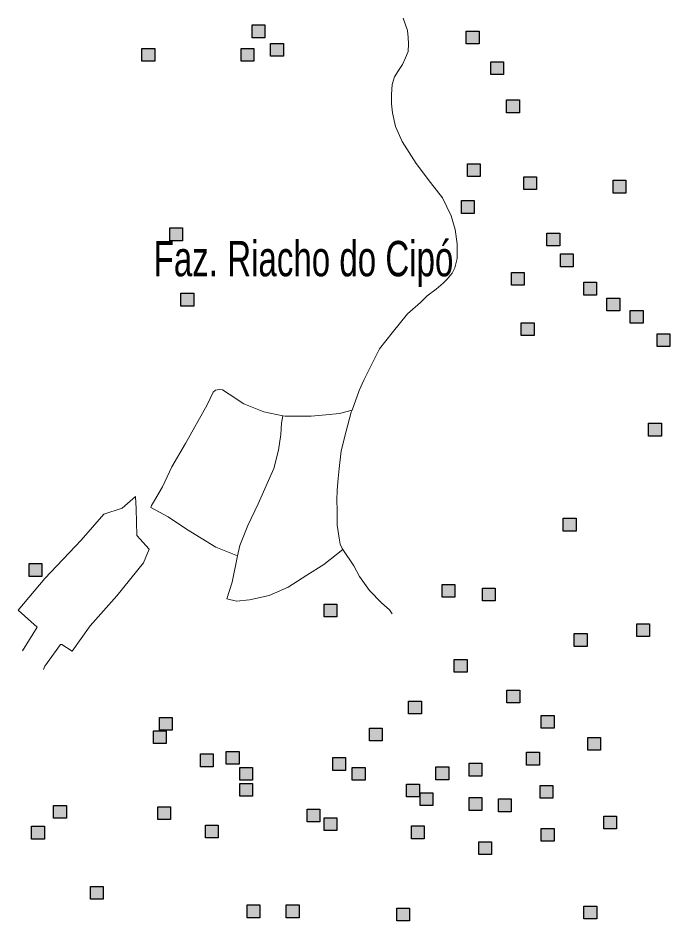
# Model space of a CAD drawing. Extents: x 445.6 to 500, y 8618.1 to 8673.4.
# Drawn here: x 466.846 to 469.797, y 8626.513 to 8630.601 of the extents above; entities that cross this region are included whole.
import ezdxf

# ---------------------------------------------------------------- set-up
doc = ezdxf.new("R2010")
doc.units = 0
doc.header["$LTSCALE"] = 0.064
doc.linetypes.add('DOT_DASHED', pattern=[7.7, 5, -1.2, 0.3, -1.2])
doc.layers.add('2', color=7, linetype='Continuous', lineweight=25)
doc.layers.add('22', color=7, linetype='DOT_DASHED', lineweight=13)
doc.layers.add('61', color=7, linetype='Continuous')

msp = doc.modelspace()

# ---------------------------------------------------------------- hatches: boundary and pattern name
at = {"layer": '2'}
for points in [[(467.9059, 8630.5696), (467.9639, 8630.5696), (467.9639, 8630.5116), (467.9059, 8630.5116)], [(468.875, 8630.5417), (468.933, 8630.5417), (468.933, 8630.4837), (468.875, 8630.4837)], [(467.9891, 8630.4862), (468.0471, 8630.4862), (468.0471, 8630.4282), (467.9891, 8630.4282)], [(467.4065, 8630.4639), (467.4645, 8630.4639), (467.4645, 8630.4059), (467.4065, 8630.4059)], [(467.8561, 8630.4639), (467.9141, 8630.4639), (467.9141, 8630.4059), (467.8561, 8630.4059)], [(468.9859, 8630.4028), (469.0439, 8630.4028), (469.0439, 8630.3448), (468.9859, 8630.3448)], [(469.0579, 8630.2305), (469.1159, 8630.2305), (469.1159, 8630.1725), (469.0579, 8630.1725)], [(468.8806, 8629.9415), (468.9386, 8629.9415), (468.9386, 8629.8835), (468.8806, 8629.8835)], [(469.1355, 8629.8828), (469.1935, 8629.8828), (469.1935, 8629.8248), (469.1355, 8629.8248)], [(469.5396, 8629.8663), (469.5976, 8629.8663), (469.5976, 8629.8083), (469.5396, 8629.8083)], [(468.8529, 8629.7747), (468.9109, 8629.7747), (468.9109, 8629.7167), (468.8529, 8629.7167)], [(467.5327, 8629.6508), (467.5907, 8629.6508), (467.5907, 8629.5928), (467.5327, 8629.5928)], [(469.2404, 8629.6273), (469.2984, 8629.6273), (469.2984, 8629.5693), (469.2404, 8629.5693)], [(469.3013, 8629.5328), (469.3593, 8629.5328), (469.3593, 8629.4748), (469.3013, 8629.4748)], [(469.0797, 8629.4495), (469.1377, 8629.4495), (469.1377, 8629.3915), (469.0797, 8629.3915)], [(469.4066, 8629.405), (469.4646, 8629.405), (469.4646, 8629.347), (469.4066, 8629.347)], [(467.5834, 8629.355), (467.6414, 8629.355), (467.6414, 8629.297), (467.5834, 8629.297)], [(469.5119, 8629.3333), (469.5699, 8629.3333), (469.5699, 8629.2753), (469.5119, 8629.2753)], [(469.6172, 8629.2772), (469.6752, 8629.2772), (469.6752, 8629.2192), (469.6172, 8629.2192)], [(469.124, 8629.2216), (469.182, 8629.2216), (469.182, 8629.1636), (469.124, 8629.1636)], [(469.7391, 8629.1716), (469.7971, 8629.1716), (469.7971, 8629.1136), (469.7391, 8629.1136)], [(469.7003, 8628.7663), (469.7583, 8628.7663), (469.7583, 8628.7083), (469.7003, 8628.7083)], [(469.3142, 8628.3364), (469.3722, 8628.3364), (469.3722, 8628.2784), (469.3142, 8628.2784)], [(466.8962, 8628.1307), (466.9542, 8628.1307), (466.9542, 8628.0727), (466.8962, 8628.0727)], [(468.7655, 8628.0363), (468.8235, 8628.0363), (468.8235, 8627.9783), (468.7655, 8627.9783)], [(468.9484, 8628.0196), (469.0064, 8628.0196), (469.0064, 8627.9616), (468.9484, 8627.9616)], [(468.2317, 8627.9473), (468.2897, 8627.9473), (468.2897, 8627.8893), (468.2317, 8627.8893)], [(469.6467, 8627.8584), (469.7047, 8627.8584), (469.7047, 8627.8004), (469.6467, 8627.8004)], [(469.364, 8627.814), (469.422, 8627.814), (469.422, 8627.756), (469.364, 8627.756)], [(468.821, 8627.6973), (468.879, 8627.6973), (468.879, 8627.6393), (468.821, 8627.6393)], [(469.0592, 8627.5583), (469.1172, 8627.5583), (469.1172, 8627.5003), (469.0592, 8627.5003)], [(468.6141, 8627.5082), (468.6721, 8627.5082), (468.6721, 8627.4502), (468.6141, 8627.4502)], [(467.4856, 8627.4343), (467.5436, 8627.4343), (467.5436, 8627.3763), (467.4856, 8627.3763)], [(469.2146, 8627.4434), (469.2726, 8627.4434), (469.2726, 8627.3854), (469.2146, 8627.3854)], [(467.4588, 8627.3738), (467.5168, 8627.3738), (467.5168, 8627.3158), (467.4588, 8627.3158)], [(468.4368, 8627.3859), (468.4948, 8627.3859), (468.4948, 8627.3279), (468.4368, 8627.3279)], [(469.4251, 8627.3434), (469.4831, 8627.3434), (469.4831, 8627.2854), (469.4251, 8627.2854)], [(467.672, 8627.2692), (467.73, 8627.2692), (467.73, 8627.2112), (467.672, 8627.2112)], [(467.7884, 8627.2803), (467.8464, 8627.2803), (467.8464, 8627.2223), (467.7884, 8627.2223)], [(468.2705, 8627.2525), (468.3285, 8627.2525), (468.3285, 8627.1945), (468.2705, 8627.1945)], [(469.1481, 8627.2767), (469.2061, 8627.2767), (469.2061, 8627.2187), (469.1481, 8627.2187)], [(467.8494, 8627.208), (467.9074, 8627.208), (467.9074, 8627.15), (467.8494, 8627.15)], [(468.3592, 8627.208), (468.4172, 8627.208), (468.4172, 8627.15), (468.3592, 8627.15)], [(468.738, 8627.21), (468.796, 8627.21), (468.796, 8627.152), (468.738, 8627.152)], [(468.8876, 8627.2267), (468.9456, 8627.2267), (468.9456, 8627.1687), (468.8876, 8627.1687)], [(467.8494, 8627.1358), (467.9074, 8627.1358), (467.9074, 8627.0778), (467.8494, 8627.0778)], [(468.605, 8627.1322), (468.663, 8627.1322), (468.663, 8627.0742), (468.605, 8627.0742)], [(469.209, 8627.1266), (469.267, 8627.1266), (469.267, 8627.0686), (469.209, 8627.0686)], [(468.6659, 8627.0933), (468.7239, 8627.0933), (468.7239, 8627.0353), (468.6659, 8627.0353)], [(468.8876, 8627.071), (468.9456, 8627.071), (468.9456, 8627.013), (468.8876, 8627.013)], [(469.0206, 8627.0655), (469.0786, 8627.0655), (469.0786, 8627.0075), (469.0206, 8627.0075)], [(467.007, 8627.0357), (467.065, 8627.0357), (467.065, 8626.9777), (467.007, 8626.9777)], [(467.4781, 8627.0302), (467.5361, 8627.0302), (467.5361, 8626.9722), (467.4781, 8626.9722)], [(468.1541, 8627.0191), (468.2121, 8627.0191), (468.2121, 8626.9611), (468.1541, 8626.9611)], [(468.2317, 8626.9802), (468.2897, 8626.9802), (468.2897, 8626.9222), (468.2317, 8626.9222)], [(469.4972, 8626.9877), (469.5552, 8626.9877), (469.5552, 8626.9297), (469.4972, 8626.9297)], [(466.9073, 8626.9412), (466.9653, 8626.9412), (466.9653, 8626.8832), (466.9073, 8626.8832)], [(467.6942, 8626.9468), (467.7522, 8626.9468), (467.7522, 8626.8888), (467.6942, 8626.8888)], [(468.6271, 8626.9432), (468.6851, 8626.9432), (468.6851, 8626.8852), (468.6271, 8626.8852)], [(469.2146, 8626.9321), (469.2726, 8626.9321), (469.2726, 8626.8741), (469.2146, 8626.8741)], [(468.9319, 8626.8709), (468.9899, 8626.8709), (468.9899, 8626.8129), (468.9319, 8626.8129)], [(467.1733, 8626.6689), (467.2313, 8626.6689), (467.2313, 8626.6109), (467.1733, 8626.6109)], [(467.8826, 8626.5855), (467.9406, 8626.5855), (467.9406, 8626.5275), (467.8826, 8626.5275)], [(468.0599, 8626.5855), (468.1179, 8626.5855), (468.1179, 8626.5275), (468.0599, 8626.5275)], [(468.5606, 8626.5708), (468.6186, 8626.5708), (468.6186, 8626.5128), (468.5606, 8626.5128)], [(469.4075, 8626.58), (469.4655, 8626.58), (469.4655, 8626.522), (469.4075, 8626.522)]]:
    msp.add_hatch(color=256, dxfattribs=at).paths.add_polyline_path(points)

# ---------------------------------------------------------------- linework, layer by layer
for points in [[(467.9059, 8630.5696), (467.9639, 8630.5696), (467.9639, 8630.5116), (467.9059, 8630.5116)], [(468.875, 8630.5417), (468.933, 8630.5417), (468.933, 8630.4837), (468.875, 8630.4837)], [(467.9891, 8630.4862), (468.0471, 8630.4862), (468.0471, 8630.4282), (467.9891, 8630.4282)], [(467.4065, 8630.4639), (467.4645, 8630.4639), (467.4645, 8630.4059), (467.4065, 8630.4059)], [(467.8561, 8630.4639), (467.9141, 8630.4639), (467.9141, 8630.4059), (467.8561, 8630.4059)], [(468.9859, 8630.4028), (469.0439, 8630.4028), (469.0439, 8630.3448), (468.9859, 8630.3448)], [(469.0579, 8630.2305), (469.1159, 8630.2305), (469.1159, 8630.1725), (469.0579, 8630.1725)], [(468.8806, 8629.9415), (468.9386, 8629.9415), (468.9386, 8629.8835), (468.8806, 8629.8835)], [(469.1355, 8629.8828), (469.1935, 8629.8828), (469.1935, 8629.8248), (469.1355, 8629.8248)], [(469.5396, 8629.8663), (469.5976, 8629.8663), (469.5976, 8629.8083), (469.5396, 8629.8083)], [(468.8529, 8629.7747), (468.9109, 8629.7747), (468.9109, 8629.7167), (468.8529, 8629.7167)], [(467.5327, 8629.6508), (467.5907, 8629.6508), (467.5907, 8629.5928), (467.5327, 8629.5928)], [(469.2404, 8629.6273), (469.2984, 8629.6273), (469.2984, 8629.5693), (469.2404, 8629.5693)], [(469.3013, 8629.5328), (469.3593, 8629.5328), (469.3593, 8629.4748), (469.3013, 8629.4748)], [(469.0797, 8629.4495), (469.1377, 8629.4495), (469.1377, 8629.3915), (469.0797, 8629.3915)], [(469.4066, 8629.405), (469.4646, 8629.405), (469.4646, 8629.347), (469.4066, 8629.347)], [(467.5834, 8629.355), (467.6414, 8629.355), (467.6414, 8629.297), (467.5834, 8629.297)], [(469.5119, 8629.3333), (469.5699, 8629.3333), (469.5699, 8629.2753), (469.5119, 8629.2753)], [(469.6172, 8629.2772), (469.6752, 8629.2772), (469.6752, 8629.2192), (469.6172, 8629.2192)], [(469.124, 8629.2216), (469.182, 8629.2216), (469.182, 8629.1636), (469.124, 8629.1636)], [(469.7391, 8629.1716), (469.7971, 8629.1716), (469.7971, 8629.1136), (469.7391, 8629.1136)], [(469.7003, 8628.7663), (469.7583, 8628.7663), (469.7583, 8628.7083), (469.7003, 8628.7083)], [(469.3142, 8628.3364), (469.3722, 8628.3364), (469.3722, 8628.2784), (469.3142, 8628.2784)], [(466.8962, 8628.1307), (466.9542, 8628.1307), (466.9542, 8628.0727), (466.8962, 8628.0727)], [(468.7655, 8628.0363), (468.8235, 8628.0363), (468.8235, 8627.9783), (468.7655, 8627.9783)], [(468.9484, 8628.0196), (469.0064, 8628.0196), (469.0064, 8627.9616), (468.9484, 8627.9616)], [(468.2317, 8627.9473), (468.2897, 8627.9473), (468.2897, 8627.8893), (468.2317, 8627.8893)], [(469.6467, 8627.8584), (469.7047, 8627.8584), (469.7047, 8627.8004), (469.6467, 8627.8004)], [(469.364, 8627.814), (469.422, 8627.814), (469.422, 8627.756), (469.364, 8627.756)], [(468.821, 8627.6973), (468.879, 8627.6973), (468.879, 8627.6393), (468.821, 8627.6393)], [(469.0592, 8627.5583), (469.1172, 8627.5583), (469.1172, 8627.5003), (469.0592, 8627.5003)], [(468.6141, 8627.5082), (468.6721, 8627.5082), (468.6721, 8627.4502), (468.6141, 8627.4502)], [(467.4856, 8627.4343), (467.5436, 8627.4343), (467.5436, 8627.3763), (467.4856, 8627.3763)], [(469.2146, 8627.4434), (469.2726, 8627.4434), (469.2726, 8627.3854), (469.2146, 8627.3854)], [(467.4588, 8627.3738), (467.5168, 8627.3738), (467.5168, 8627.3158), (467.4588, 8627.3158)], [(468.4368, 8627.3859), (468.4948, 8627.3859), (468.4948, 8627.3279), (468.4368, 8627.3279)], [(469.4251, 8627.3434), (469.4831, 8627.3434), (469.4831, 8627.2854), (469.4251, 8627.2854)], [(467.672, 8627.2692), (467.73, 8627.2692), (467.73, 8627.2112), (467.672, 8627.2112)], [(467.7884, 8627.2803), (467.8464, 8627.2803), (467.8464, 8627.2223), (467.7884, 8627.2223)], [(468.2705, 8627.2525), (468.3285, 8627.2525), (468.3285, 8627.1945), (468.2705, 8627.1945)], [(469.1481, 8627.2767), (469.2061, 8627.2767), (469.2061, 8627.2187), (469.1481, 8627.2187)], [(467.8494, 8627.208), (467.9074, 8627.208), (467.9074, 8627.15), (467.8494, 8627.15)], [(468.3592, 8627.208), (468.4172, 8627.208), (468.4172, 8627.15), (468.3592, 8627.15)], [(468.738, 8627.21), (468.796, 8627.21), (468.796, 8627.152), (468.738, 8627.152)], [(468.8876, 8627.2267), (468.9456, 8627.2267), (468.9456, 8627.1687), (468.8876, 8627.1687)], [(467.8494, 8627.1358), (467.9074, 8627.1358), (467.9074, 8627.0778), (467.8494, 8627.0778)], [(468.605, 8627.1322), (468.663, 8627.1322), (468.663, 8627.0742), (468.605, 8627.0742)], [(469.209, 8627.1266), (469.267, 8627.1266), (469.267, 8627.0686), (469.209, 8627.0686)], [(468.6659, 8627.0933), (468.7239, 8627.0933), (468.7239, 8627.0353), (468.6659, 8627.0353)], [(468.8876, 8627.071), (468.9456, 8627.071), (468.9456, 8627.013), (468.8876, 8627.013)], [(469.0206, 8627.0655), (469.0786, 8627.0655), (469.0786, 8627.0075), (469.0206, 8627.0075)], [(467.007, 8627.0357), (467.065, 8627.0357), (467.065, 8626.9777), (467.007, 8626.9777)], [(467.4781, 8627.0302), (467.5361, 8627.0302), (467.5361, 8626.9722), (467.4781, 8626.9722)], [(468.1541, 8627.0191), (468.2121, 8627.0191), (468.2121, 8626.9611), (468.1541, 8626.9611)], [(468.2317, 8626.9802), (468.2897, 8626.9802), (468.2897, 8626.9222), (468.2317, 8626.9222)], [(469.4972, 8626.9877), (469.5552, 8626.9877), (469.5552, 8626.9297), (469.4972, 8626.9297)], [(466.9073, 8626.9412), (466.9653, 8626.9412), (466.9653, 8626.8832), (466.9073, 8626.8832)], [(467.6942, 8626.9468), (467.7522, 8626.9468), (467.7522, 8626.8888), (467.6942, 8626.8888)], [(468.6271, 8626.9432), (468.6851, 8626.9432), (468.6851, 8626.8852), (468.6271, 8626.8852)], [(469.2146, 8626.9321), (469.2726, 8626.9321), (469.2726, 8626.8741), (469.2146, 8626.8741)], [(468.9319, 8626.8709), (468.9899, 8626.8709), (468.9899, 8626.8129), (468.9319, 8626.8129)], [(467.1733, 8626.6689), (467.2313, 8626.6689), (467.2313, 8626.6109), (467.1733, 8626.6109)], [(467.8826, 8626.5855), (467.9406, 8626.5855), (467.9406, 8626.5275), (467.8826, 8626.5275)], [(468.0599, 8626.5855), (468.1179, 8626.5855), (468.1179, 8626.5275), (468.0599, 8626.5275)], [(468.5606, 8626.5708), (468.6186, 8626.5708), (468.6186, 8626.5128), (468.5606, 8626.5128)], [(469.4075, 8626.58), (469.4655, 8626.58), (469.4655, 8626.522), (469.4075, 8626.522)]]:
    msp.add_lwpolyline(points, close=True, dxfattribs=at)
at = {"layer": '22'}
for points in [[(468.5887, 8630.601), (468.6093, 8630.5451), (468.6115, 8630.5134), (468.6138, 8630.4839), (468.6115, 8630.4499), (468.6002, 8630.4205), (468.5866, 8630.391), (468.5684, 8630.3638), (468.5503, 8630.3344), (468.5389, 8630.3004), (468.5367, 8630.2551), (468.5367, 8630.212), (468.5412, 8630.1712), (468.5548, 8630.1101), (468.5843, 8630.0421), (468.6478, 8629.9432), (468.7136, 8629.8571), (468.768, 8629.7868), (468.8066, 8629.7053), (468.8247, 8629.6441), (468.8338, 8629.5784), (468.8338, 8629.5127), (468.8228, 8629.4701), (468.8115, 8629.4452), (468.7888, 8629.418), (468.7707, 8629.3999), (468.7389, 8629.3727), (468.6981, 8629.3432), (468.6686, 8629.3138), (468.6096, 8629.2617), (468.5392, 8629.1756), (468.4825, 8629.1031), (468.4553, 8629.0487), (468.4114, 8628.9615), (468.3909, 8628.9139), (468.3582, 8628.8263)], [(468.0453, 8628.7998), (467.9592, 8628.8177), (467.8674, 8628.8536), (467.8016, 8628.8975), (467.7716, 8628.9174), (467.7576, 8628.9194), (467.7397, 8628.9154), (467.7297, 8628.9074), (467.7018, 8628.8496), (467.604, 8628.6743), (467.5421, 8628.5686), (467.5002, 8628.4789), (467.4635, 8628.416), (467.4496, 8628.394), (467.4476, 8628.3841), (467.5254, 8628.3422), (467.6092, 8628.2864), (467.741, 8628.2047), (467.84, 8628.1656)], [(468.3582, 8628.8263), (468.3005, 8628.8098), (468.2387, 8628.8038), (468.1728, 8628.7978), (468.055, 8628.7978), (468.0453, 8628.7998)], [(468.3582, 8628.8263), (468.3546, 8628.8165), (468.3319, 8628.7304), (468.3093, 8628.642), (468.3, 8628.5614), (468.2954, 8628.5161), (468.2909, 8628.464), (468.2886, 8628.4187), (468.2909, 8628.3734), (468.2909, 8628.3054), (468.3, 8628.2465), (468.3045, 8628.2193), (468.3136, 8628.1989), (468.3164, 8628.1947)], [(467.84, 8628.1656), (467.8495, 8628.2121), (467.8855, 8628.3038), (467.9334, 8628.4014), (468.0032, 8628.5621), (468.0252, 8628.6438), (468.0352, 8628.7156), (468.0392, 8628.7674), (468.0453, 8628.7998)], [(466.8658, 8627.7352), (466.933, 8627.8426), (466.846, 8627.9201), (466.9671, 8628.0628), (467.1317, 8628.2364), (467.2342, 8628.3542), (467.318, 8628.3821), (467.377, 8628.4348), (467.3801, 8628.379), (467.3832, 8628.2581), (467.4391, 8628.1961), (467.4143, 8628.1341), (467.2932, 8627.9852), (467.1721, 8627.8488), (467.0913, 8627.7341), (467.0448, 8627.7651), (467.0386, 8627.7651), (466.9671, 8627.6659), (466.9615, 8627.652)], [(468.3164, 8628.1947), (468.2308, 8628.1264), (468.1529, 8628.0786), (468.0691, 8628.0247), (467.9833, 8627.9869), (467.8935, 8627.9669), (467.8356, 8627.961), (467.7917, 8627.9709), (467.8156, 8628.0467), (467.84, 8628.1656)], [(468.3164, 8628.1947), (468.3663, 8628.1206), (468.3913, 8628.073), (468.4367, 8628.0096), (468.4911, 8627.9529), (468.5274, 8627.9212), (468.539, 8627.9033)]]:
    msp.add_lwpolyline(points, dxfattribs=at)

# ---------------------------------------------------------------- texts
at = {"layer": '61', "width": 0.7}
msp.add_text('Faz. Riacho do Cipó', height=0.16, dxfattribs=at).set_placement((467.4598, 8629.4318))

doc.saveas('drawing.dxf')
